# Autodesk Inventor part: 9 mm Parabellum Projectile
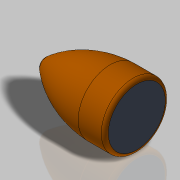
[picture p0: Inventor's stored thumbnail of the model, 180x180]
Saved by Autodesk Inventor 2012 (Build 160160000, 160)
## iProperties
Company: MH Vaaben Teknik
Category: Sten MK II Magazine
Created: 2011-12
Part Number: 9 mm Parabellum Projectile
Material: Copper
Document SubType Name: Modeling
Designer: Michael Høgh
Density: 8.94 g/cm^3
Project: Sten MK II
Engineer: MH Vaaben Teknik
Author: Michael Høgh
Title: 9 mm Parabellum Projectile
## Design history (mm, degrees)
sketch "Sketch1"
  geometry: L1 (-1.652, 4.515)-(2.102, 4.515); L2 (2.102, 4.515)-(2.102, 0); L3 (-12.716, 0)-(3.586, 0); A1 r 1.3 centre (-9.798, 0) between (-10.596, 1.026) and (-11.098, 0); A2 r 14.621 centre (-1.105, -10.095) between (-1.652, 4.515) and (-10.596, 1.026); 1 further point
  constraints: 6 end point, 4 point on circle, 2 centre point, 2 perpendicular
  dimensions: "d34" = 2.6 diameter of A1; "d37" = 13.2 distance of L2.end A1.end
feature "RevolutionSrf1" sketch "Sketch1" dims angle "d38" = 90 deg
fillet "Fillet3" dims "d39" = 0.5
body "Solid2"
body "Srf1"
other parameters: "d0" = 4.98, "d2" = 4.395, "d4" = 4.965, "d33" = 4.515
